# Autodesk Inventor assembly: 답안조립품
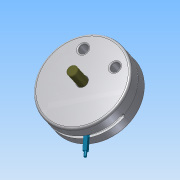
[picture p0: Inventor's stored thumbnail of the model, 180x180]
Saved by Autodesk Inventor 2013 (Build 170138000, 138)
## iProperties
Created: 2015-04
Part Number: 답안조립품
Document SubType Name: Assembly
Designer: Administrator
Author: Administrator
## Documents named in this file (10)
- C:\Users\Administrator\Desktop\450406V1047\답안조립품.iam
- C:\Users\Administrator\Desktop\450406V1047\본체.ipt
- C:\Users\Administrator\Desktop\450406V1047\M 10 x 35.ipt
- C:\Users\Administrator\Desktop\450406V1047\덮개.ipt
- C:\Users\Administrator\Desktop\450406V1047\멈춤링.ipt
- C:\Users\Administrator\Desktop\450406V1047\베어링62_22.ipt
- C:\Users\Administrator\Desktop\450406V1047\슬라이더.ipt
- C:\Users\Administrator\Desktop\450406V1047\슬라이더2.ipt
- C:\Users\Administrator\Desktop\450406V1047\축.ipt
- C:\Users\Administrator\Desktop\450406V1047\평행핀.ipt
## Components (2 placed, 1 different names)
1. M 10 x 35:1
2. M 10 x 35:2
